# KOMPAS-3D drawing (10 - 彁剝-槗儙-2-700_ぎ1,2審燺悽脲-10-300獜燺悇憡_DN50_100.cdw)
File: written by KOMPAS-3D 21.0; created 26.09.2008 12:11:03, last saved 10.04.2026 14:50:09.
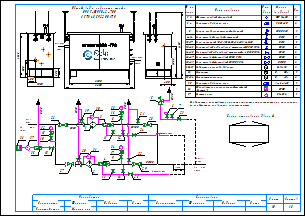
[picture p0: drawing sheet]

Sheets 1-2: A3, landscape

Document properties: Наименование: Макро:21; Автор: RaskoAdmin; Форматы листов документа: 2xA3; Полное имя файла: \\UR38nt01\Departments\КТО\КБ ПУРДГ\Заявки\Прайс-лист на типовые шкафы ГРПШ\ПРДГ_стандарт_20_03_2026\ПРДГ с РДСК\ПРДГ-ШУГО-2-700_до1,2МПа_Рвых-10-300кПа_РДСК_DN50_100.cdw

Title block, sheet 1: Наименование: Пункт учета газа / ПУГ-Ш-400-Р / ЛГТИ.485922.001ТУ; designation: ЛГТИ.03.4411141; sheet number: 1; Количество листов документа: 2; organisation: ООО "ЭЛЬСТЕР Газэлектроника"; Форматы листов документа: A3; stored path: C:\Рабочие документы\Компас\ПУГ\Схема.cdw; Разработал: Устинов; Проверил: Кошкин; Утвердил: Кошкин
Title block, sheet 2: sheet number: 2; stored path: D:\Рабочие документы\Заявки\ПУРДГ\ПУРДГ-ШУЭО-2-100-Р 4411220.cdw; designation, second copy: ЛГТИ.03.4411141-

Views: Вид 1, Вид 2
Referenced files: wcvoit.frw
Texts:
  Normal
  Вход
  газа
  PDI
  Выход
  Р=     кПа
  DN100
  DN50
  DN20
  Импульс DN20
  ≥5DN
  HYSWLongFangSong
  № на
  схеме
  Усл.
  обозн.
  Марка
  (модель)
  Кол.
  Фильтр газовый фланцевый
  ФГ 16-50
  Регулятор давления газа
  РДCК-50
  Клапан предохранительный сбросной
  КПС DN20
  Кран шаровой газовый латунный
  DN15
  Кран кнопочный VE-РАСКО-НЗ-1,6-G1/2-М20
  Кран шаровой "под приварку" штуцерный DN20 PN16
  Кран шаровой "под приварку" штуцерный п/п DN20 PN16
  Кран шаровой фланцевый DN50 PN16
  Кран шаровой фланцевый DN100 PN16
  Индикатор перепада давления
  Delta 15
  Манометр
  Манометр-напоромер
  0...     МПа
  0...     кПа
  Обогреватель газогорелочный шкафной
  (Эльтон")
  Счетчик газа
  Venio-A-15
  ОГШН
  BK-G1,6
  Общий вид и габариты шкафа
  ПРДГ-ШУГО-2-700
  Выход газа
  Вход газа
  Схема открывания дверей
  Р=        МПа
  logo-rasko-ge.png
  Предприятие изготовитель может заменять комплектующие на аналогичные,
  не ухудшающие заявленных характеристик.
  Должность
  Конструктор
  Фамилия
  Подпись
  Дата
  Согласовано
  Максимкин
  Лист
  Листов
  POLYLINE_STYLE_0.18_RGB_0_0_0
  POLYLINE_STYLE_0.50_RGB_0_0_0
  POLYLINE_STYLE_0.34_RGB_0_0_0
  PHANTOM_RGB_0_0_0_SC_1_THICK_0.18
  K5LT_THIN_RGB_0_0_0_THICK_0.18
  K5LT32769_RGB_0_0_0_THICK_0.18
  K5LT12_RGB_0_0_0_SC_1_THICK_0.18
  K5LT_DASHED_RGB_0_0_0_SC_1_THICK_0.18
  ACISOTGL_RGB_0_0_0_SC_0.8_THICK_0.25
  CONTINUOUS_RGB_0_127_31_THICK_0.3
  CONTINUOUS_RGB_0_0_255_THICK_0.35
  CONTINUOUS_RGB_255_0_0_THICK_0.35
  POLYLINE_STYLE_0.25_RGB_0_0_0
  CONTINUOUS_RGB_0_0_0_THICK_0.5
  POLYLINE_STYLE_0.35_RGB_0_0_255
  CONTINUOUS_RGB_0_0_0_THICK_0.4
  CONTINUOUS_RGB_0_0_0_THICK_0.35
  Без оформления
Dimensions and other numbers on the sheet: 1; 2; 3; 4; 5; 10; 27; 28; 29; 23; 8; 12; 18; 19; 20; 21; 22; 25; 24; 30; 31; 15; 16; 35; 36; 26; 6; 7; 11; 14; 13; 33; 1, 2; 3, 4; 6-14; 9; 15-17; 18-23; 24-25; 26-27; 28-29; 30-31; 32; 33-34; 37; 400; 1050; 500; 305; 2300; 1565; 2600; 17; 34; 1000; 4130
